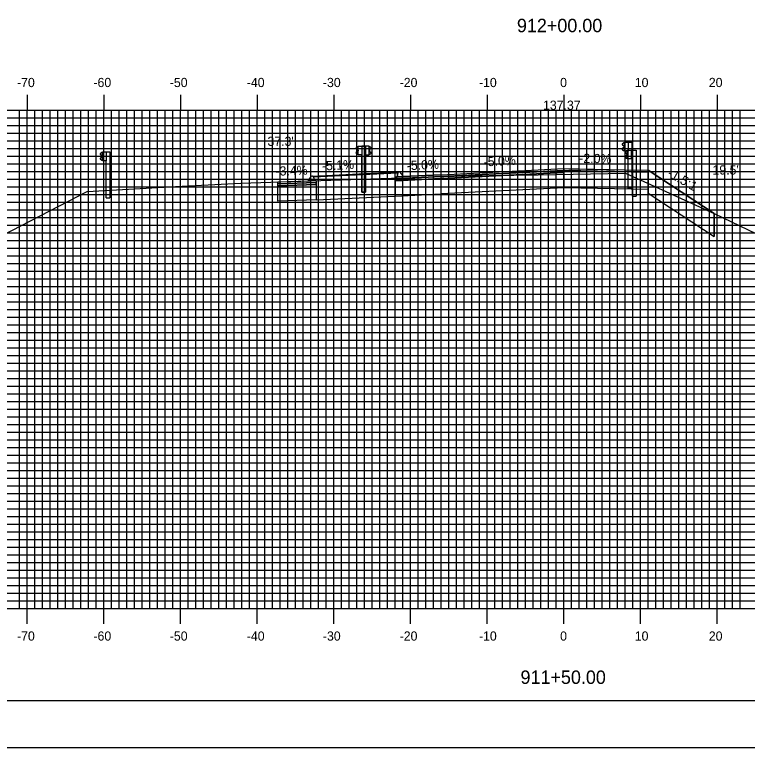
# Model space of a CAD drawing. Extents: x 859865 to 860208, y 364765 to 364985.
# Drawn here: x 859958.8 to 860054.3, y 364765.2 to 364860.7 of the extents above; entities that cross this region are included whole.
import ezdxf

# ---------------------------------------------------------------- set-up
doc = ezdxf.new("R2010")
doc.units = 0
for name, color, linetype in [('ANNOTATION', 7, 'Continuous'), ('BORDER', 7, 'Continuous'), ('D_Curb_Type_3M2_Lt', 7, 'Continuous'), ('D_Curb_Type_3M2_Rt', 7, 'Continuous'), ('D_Guardrail_Beam_Rt', 7, 'Continuous'), ('D_Roadway_Centerline', 7, 'Continuous'), ('D_Roadway_Centerline_Text', 7, 'Continuous'), ('D_Roadway_Edge_Shoulder', 7, 'Continuous'), ('D_Roadway_Edge_TW', 7, 'Continuous'), ('D_Roadway_FinishedGrade', 7, 'Continuous'), ('D_Roadway_Pavement', 7, 'Continuous'), ('D_Roadway_SubGrade', 7, 'Continuous'), ('D_Text_Standard', 7, 'Continuous'), ('H_V ANNOTATION', 7, 'Continuous'), ('M_Guardrail', 7, 'Continuous'), ('M_Roadway_Centerline', 7, 'Continuous'), ('MAJOR', 7, 'Continuous'), ('MINOR', 7, 'Continuous'), ('PATTERNING', 7, 'Continuous'), ('PLOT BOUNDARY', 7, 'Continuous'), ('S_Roadway_Centerline', 7, 'Continuous')]:
    doc.layers.add(name, color=color, linetype=linetype)

msp = doc.modelspace()

# ---------------------------------------------------------------- linework, layer by layer
at = {"layer": 'BORDER'}
msp.add_lwpolyline([(859880.786, 364771.302), (860200.786, 364771.302), (860200.786, 364981.302), (859880.786, 364981.302)], close=True, dxfattribs=at)
at = {"layer": 'D_Curb_Type_3M2_Lt'}
for p, q in [((860008.744, 364840.114), (860008.636, 364839.62)), ((860008.636, 364839.62), (860009.386, 364839.62)), ((860008.88, 364840.243), (860008.885, 364840.243)), ((860009.386, 364839.787), (860009.032, 364840.189)), ((860009.386, 364839.62), (860009.386, 364839.787))]:
    msp.add_line(p, q, dxfattribs=at)
msp.add_arc((860008.907, 364840.079), 0.167, 41.38705, 167.66476, dxfattribs=at)
at = {"layer": 'D_Curb_Type_3M2_Rt'}
for p, q in [((859997.1, 364839.245), (859997.454, 364839.647)), ((859997.742, 364839.572), (859997.85, 364839.078)), ((859997.1, 364839.078), (859997.1, 364839.245)), ((859997.85, 364839.078), (859997.1, 364839.078))]:
    msp.add_line(p, q, dxfattribs=at)
msp.add_arc((859997.579, 364839.537), 0.167, 12.33524, 138.61295, dxfattribs=at)
at = {"layer": 'D_Guardrail_Beam_Rt'}
for p, q in [((860038.567, 364842.989), (860038.423, 364842.889)), ((860038.423, 364842.746), (860038.619, 364842.61)), ((860038.619, 364842.411), (860038.423, 364842.275)), ((860038.657, 364843.01), (860038.583, 364842.996)), ((860038.652, 364842.545), (860038.652, 364842.475)), ((860038.657, 364843.094), (860039.344, 364843.094)), ((860038.657, 364841.927), (860038.657, 364843.094)), ((860039.177, 364843.094), (860039.177, 364841.927)), ((860039.282, 364843.094), (860039.282, 364841.927)), ((860039.344, 364843.094), (860039.815, 364843.094)), ((860039.344, 364843.094), (860039.344, 364841.927)), ((860039.815, 364843.094), (860039.815, 364837.094)), ((860038.423, 364842.131), (860038.567, 364842.032)), ((860038.583, 364842.025), (860038.657, 364842.01)), ((860039.344, 364841.927), (860038.657, 364841.927)), ((860039.323, 364837.094), (860039.323, 364841.927)), ((860039.323, 364837.094), (860039.815, 364837.094))]:
    msp.add_line(p, q, dxfattribs=at)
for centre, major_axis, start_param, end_param in [((860038.474, 364842.817), (-0.0877, 0), 5.323254, 7.243116), ((860038.591, 364842.955), (-0.0417, 0), 4.907132, 5.323254), ((860038.573, 364842.545), (0.0789, 0), 0, 0.959931), ((860038.573, 364842.475), (0.0789, 0), 5.323254, 6.283185), ((860038.474, 364842.203), (-0.0877, 0), 5.323254, 7.243116), ((860038.591, 364842.065), (-0.0417, 0), 0.959931, 1.376053)]:
    msp.add_ellipse(centre, major_axis=major_axis, ratio=0.995501, start_param=start_param, end_param=end_param, dxfattribs=at)
at = {"layer": 'D_Roadway_Centerline'}
for points in [[(860009.387, 364839.62), (860010.325, 364839.667), (860014.384, 364839.87), (860014.386, 364839.87), (860030.387, 364840.67), (860031.027, 364840.657), (860038.382, 364840.51), (860038.386, 364840.51), (860041.387, 364840.45), (860049.995, 364834.792)], [(859993.1, 364838.943), (859993.316, 364838.951), (859997.1, 364839.078)]]:
    msp.add_lwpolyline(points, dxfattribs=at)
at = {"layer": 'D_Roadway_Edge_Shoulder'}
for points in [[(860030.387, 364840.67), (860038.386, 364840.51), (860038.386, 364840.51), (860041.386, 364840.45), (860041.386, 364840.2), (860030.387, 364840.42)], [(860014.386, 364839.87), (860009.386, 364839.62), (860008.386, 364839.57), (860008.386, 364839.32), (860014.386, 364839.62)], [(859993.1, 364838.943), (859997.1, 364839.078), (859998.1, 364839.111), (859998.1, 364838.861), (859993.1, 364838.693)]]:
    msp.add_lwpolyline(points, close=True, dxfattribs=at)
at = {"layer": 'D_Roadway_Edge_TW'}
msp.add_lwpolyline([(860014.386, 364839.87), (860030.387, 364840.67), (860030.387, 364840.42), (860014.386, 364839.62)], close=True, dxfattribs=at)
at = {"layer": 'D_Roadway_FinishedGrade'}
msp.add_line((860049.995, 364834.792), (860049.995, 364831.792), dxfattribs=at)
for points in [[(860041.386, 364840.45), (860042.886, 364839.45), (860049.995, 364834.792)], [(860041.387, 364840.45), (860041.387, 364837.45), (860049.995, 364831.792)], [(859997.621, 364839.698), (860008.865, 364840.24)]]:
    msp.add_lwpolyline(points, dxfattribs=at)
at = {"layer": 'D_Roadway_Pavement'}
for points in [[(860014.386, 364839.62), (860030.387, 364840.42), (860030.387, 364840.17), (860014.386, 364839.37)], [(860014.386, 364839.62), (860008.386, 364839.32), (860008.386, 364839.07), (860014.386, 364839.37)], [(859993.1, 364838.693), (859998.1, 364838.861), (859998.1, 364838.611), (859993.1, 364838.443)]]:
    msp.add_lwpolyline(points, close=True, dxfattribs=at)
msp.add_lwpolyline([(860030.387, 364840.42), (860030.387, 364840.17)], dxfattribs=at)
msp.add_lwpolyline([(860030.387, 364840.42), (860030.387, 364840.17)], dxfattribs=at)
at = {"layer": 'D_Roadway_SubGrade'}
for points in [[(860030.387, 364840.17), (860030.387, 364840.42), (860041.386, 364840.2), (860041.386, 364840.45), (860041.387, 364837.95), (860030.387, 364838.17)], [(859998.1, 364839.111), (859998.1, 364836.611), (860008.386, 364837.07), (860008.386, 364839.07), (860008.386, 364839.32), (860008.386, 364839.57), (860008.628, 364839.582), (860008.734, 364840.067), (859997.75, 364839.534), (859997.845, 364839.103)], [(860014.386, 364839.37), (860030.387, 364840.17), (860030.387, 364838.17), (860014.386, 364837.37)], [(859993.1, 364838.443), (859998.1, 364838.611), (859998.1, 364838.861), (859998.1, 364836.611), (859993.1, 364836.443)], [(860014.386, 364839.37), (860008.386, 364839.07), (860008.386, 364839.32), (860008.386, 364837.07), (860014.386, 364837.37)]]:
    msp.add_lwpolyline(points, close=True, dxfattribs=at)
at = {"layer": 'M_Guardrail'}
for p, q in [((860003.459, 364843.517), (860003.316, 364843.417)), ((860003.316, 364843.274), (860003.511, 364843.138)), ((860003.558, 364843.538), (860003.476, 364843.524)), ((860003.558, 364843.611), (860004.048, 364843.611)), ((860003.558, 364842.445), (860003.558, 364843.611)), ((860004.035, 364843.612), (860004.035, 364837.612)), ((860004.527, 364843.612), (860004.035, 364843.612)), ((860004.048, 364843.611), (860004.539, 364843.611)), ((860004.048, 364843.611), (860004.048, 364842.445)), ((860005.017, 364843.612), (860004.527, 364843.612)), ((860004.527, 364843.612), (860004.527, 364842.445)), ((860004.539, 364843.611), (860004.539, 364837.611)), ((860005.017, 364842.445), (860005.017, 364843.612)), ((860005.017, 364843.539), (860005.099, 364843.525)), ((860005.259, 364843.275), (860005.063, 364843.139)), ((860005.115, 364843.518), (860005.259, 364843.418)), ((860038.18, 364844.01), (860038.036, 364843.91)), ((860038.036, 364843.767), (860038.232, 364843.631)), ((860038.232, 364843.411), (860038.036, 364843.275)), ((860038.279, 364844.031), (860038.197, 364844.017)), ((860038.265, 364843.566), (860038.265, 364843.475)), ((860038.279, 364844.104), (860038.768, 364844.104)), ((860038.279, 364842.938), (860038.279, 364844.104)), ((860038.768, 364844.104), (860039.26, 364844.104)), ((860038.768, 364844.104), (860038.768, 364842.938)), ((860039.26, 364844.104), (860039.26, 364838.104)), ((859970.108, 364842.76), (859969.964, 364842.66)), ((859969.964, 364842.517), (859970.16, 364842.38)), ((859970.206, 364842.781), (859970.124, 364842.766)), ((859970.193, 364842.316), (859970.193, 364842.225)), ((859970.206, 364842.854), (859970.696, 364842.854)), ((859970.206, 364841.687), (859970.206, 364842.854)), ((859970.696, 364842.854), (859971.188, 364842.854)), ((859970.696, 364842.854), (859970.696, 364841.687)), ((859971.188, 364842.854), (859971.188, 364836.854)), ((860003.511, 364842.918), (860003.316, 364842.782)), ((860003.316, 364842.639), (860003.459, 364842.539)), ((860003.476, 364842.532), (860003.558, 364842.517)), ((860003.545, 364843.073), (860003.545, 364842.982)), ((860004.048, 364842.445), (860003.558, 364842.445)), ((860004.048, 364837.611), (860004.048, 364842.445)), ((860004.527, 364837.612), (860004.527, 364842.445)), ((860004.527, 364842.445), (860005.017, 364842.445)), ((860005.099, 364842.533), (860005.017, 364842.518)), ((860005.03, 364843.074), (860005.03, 364842.983)), ((860005.063, 364842.919), (860005.259, 364842.783)), ((860005.259, 364842.64), (860005.115, 364842.54)), ((860038.036, 364843.132), (860038.18, 364843.032)), ((860038.197, 364843.025), (860038.279, 364843.011)), ((860038.768, 364842.938), (860038.279, 364842.938)), ((860038.768, 364838.104), (860038.768, 364842.938)), ((859970.16, 364842.161), (859969.964, 364842.024)), ((859969.964, 364841.881), (859970.108, 364841.781)), ((859970.124, 364841.774), (859970.206, 364841.76)), ((859970.696, 364841.687), (859970.206, 364841.687)), ((859970.696, 364836.854), (859970.696, 364841.687)), ((860004.527, 364837.612), (860004.035, 364837.612)), ((860004.048, 364837.611), (860004.539, 364837.611)), ((860038.768, 364838.104), (860039.26, 364838.104)), ((859970.696, 364836.854), (859971.188, 364836.854))]:
    msp.add_line(p, q, dxfattribs=at)
for centre, major_axis, start_param, end_param in [((860003.366, 364843.345), (-0.0877, 0), 5.323254, 7.243116), ((860003.483, 364843.483), (-0.0417, 0), 4.886922, 5.323254), ((860005.091, 364843.484), (0.0417, 0), 0.959931, 1.396263), ((860005.208, 364843.346), (0.0877, 0), 5.323254, 7.243116), ((860038.087, 364843.839), (-0.0877, 0), 5.323254, 7.243116), ((860038.087, 364843.203), (-0.0877, 0), 5.323254, 7.243116), ((860038.204, 364843.976), (-0.0417, 0), 4.886922, 5.323254), ((860038.187, 364843.566), (0.0789, 0), 0, 0.959931), ((860038.187, 364843.475), (0.0789, 0), 5.323254, 6.283185), ((859970.014, 364842.588), (-0.0877, 0), 5.323254, 7.243116), ((859970.132, 364842.726), (-0.0417, 0), 4.886922, 5.323254), ((859970.114, 364842.316), (0.0789, 0), 0, 0.959931), ((860003.366, 364842.71), (-0.0877, 0), 5.323254, 7.243116), ((860003.483, 364842.573), (-0.0417, 0), 0.959931, 1.396263), ((860003.466, 364843.073), (0.0789, 0), 0, 0.959931), ((860003.466, 364842.982), (0.0789, 0), 5.323254, 6.283185), ((860005.109, 364843.074), (-0.0789, 0), 5.323254, 6.283185), ((860005.109, 364842.983), (-0.0789, 0), 6.283185, 7.243116), ((860005.091, 364842.574), (0.0417, 0), 4.886922, 5.323254), ((860005.208, 364842.711), (0.0877, 0), 5.323254, 7.243116), ((860038.204, 364843.066), (-0.0417, 0), 0.959931, 1.396263), ((859970.014, 364841.953), (-0.0877, 0), 5.323254, 7.243116), ((859970.132, 364841.815), (-0.0417, 0), 0.959931, 1.396263), ((859970.114, 364842.225), (0.0789, 0), 5.323254, 6.283185)]:
    msp.add_ellipse(centre, major_axis=major_axis, ratio=0.995501, start_param=start_param, end_param=end_param, dxfattribs=at)
at = {"layer": 'MAJOR'}
for p, q in [((859960.386, 364850.306), (859960.386, 364848.302)), ((859970.386, 364850.306), (859970.386, 364848.302)), ((859980.386, 364850.306), (859980.386, 364848.302)), ((859990.386, 364850.306), (859990.386, 364848.302)), ((860000.386, 364850.306), (860000.386, 364848.302)), ((860010.386, 364850.306), (860010.386, 364848.302)), ((860020.386, 364850.306), (860020.386, 364848.302)), ((860030.386, 364850.306), (860030.386, 364848.302)), ((860040.386, 364850.306), (860040.386, 364848.302)), ((860050.386, 364850.306), (860050.386, 364848.302)), ((859890.386, 364848.302), (860170.386, 364848.302)), ((859890.386, 364848.302), (860170.386, 364848.302)), ((859960.386, 364783.302), (859960.386, 364848.302)), ((859970.386, 364783.302), (859970.386, 364848.302)), ((859980.386, 364783.302), (859980.386, 364848.302)), ((859990.386, 364783.302), (859990.386, 364848.302)), ((860000.386, 364783.302), (860000.386, 364848.302)), ((860010.386, 364783.302), (860010.386, 364848.302)), ((860020.386, 364783.302), (860020.386, 364848.302)), ((860030.386, 364783.302), (860030.386, 364848.302)), ((860040.386, 364783.302), (860040.386, 364848.302)), ((860050.386, 364783.302), (860050.386, 364848.302)), ((859890.386, 364843.302), (860170.386, 364843.302)), ((859890.386, 364838.302), (860170.386, 364838.302)), ((859890.386, 364833.302), (860170.386, 364833.302)), ((859890.386, 364828.302), (860170.386, 364828.302)), ((859890.386, 364823.302), (860170.386, 364823.302)), ((859890.386, 364818.302), (860170.386, 364818.302)), ((859890.386, 364813.302), (860170.386, 364813.302)), ((859890.386, 364808.302), (860170.386, 364808.302)), ((859890.386, 364803.302), (860170.386, 364803.302)), ((859890.386, 364798.302), (860170.386, 364798.302)), ((859890.386, 364793.302), (860170.386, 364793.302)), ((859890.386, 364788.302), (860170.386, 364788.302)), ((859890.386, 364783.302), (860170.386, 364783.302)), ((859890.386, 364783.302), (860170.386, 364783.302)), ((859960.386, 364781.298), (859960.386, 364783.302)), ((859970.386, 364781.298), (859970.386, 364783.302)), ((859980.386, 364781.298), (859980.386, 364783.302)), ((859990.386, 364781.298), (859990.386, 364783.302)), ((860000.386, 364781.298), (860000.386, 364783.302)), ((860010.386, 364781.298), (860010.386, 364783.302)), ((860020.386, 364781.298), (860020.386, 364783.302)), ((860030.386, 364781.298), (860030.386, 364783.302)), ((860040.386, 364781.298), (860040.386, 364783.302)), ((860050.386, 364781.298), (860050.386, 364783.302))]:
    msp.add_line(p, q, dxfattribs=at)
at = {"layer": 'MINOR'}
for p, q in [((859959.386, 364783.302), (859959.386, 364848.302)), ((859961.386, 364783.302), (859961.386, 364848.302)), ((859962.386, 364783.302), (859962.386, 364848.302)), ((859963.386, 364783.302), (859963.386, 364848.302)), ((859964.386, 364783.302), (859964.386, 364848.302)), ((859965.386, 364783.302), (859965.386, 364848.302)), ((859966.386, 364783.302), (859966.386, 364848.302)), ((859967.386, 364783.302), (859967.386, 364848.302)), ((859968.386, 364783.302), (859968.386, 364848.302)), ((859969.386, 364783.302), (859969.386, 364848.302)), ((859971.386, 364783.302), (859971.386, 364848.302)), ((859972.386, 364783.302), (859972.386, 364848.302)), ((859973.386, 364783.302), (859973.386, 364848.302)), ((859974.386, 364783.302), (859974.386, 364848.302)), ((859975.386, 364783.302), (859975.386, 364848.302)), ((859976.386, 364783.302), (859976.386, 364848.302)), ((859977.386, 364783.302), (859977.386, 364848.302)), ((859978.386, 364783.302), (859978.386, 364848.302)), ((859979.386, 364783.302), (859979.386, 364848.302)), ((859981.386, 364783.302), (859981.386, 364848.302)), ((859982.386, 364783.302), (859982.386, 364848.302)), ((859983.386, 364783.302), (859983.386, 364848.302)), ((859984.386, 364783.302), (859984.386, 364848.302)), ((859985.386, 364783.302), (859985.386, 364848.302)), ((859986.386, 364783.302), (859986.386, 364848.302)), ((859987.386, 364783.302), (859987.386, 364848.302)), ((859988.386, 364783.302), (859988.386, 364848.302)), ((859989.386, 364783.302), (859989.386, 364848.302)), ((859991.386, 364783.302), (859991.386, 364848.302)), ((859992.386, 364783.302), (859992.386, 364848.302)), ((859993.386, 364783.302), (859993.386, 364848.302)), ((859994.386, 364783.302), (859994.386, 364848.302)), ((859995.386, 364783.302), (859995.386, 364848.302)), ((859996.386, 364783.302), (859996.386, 364848.302)), ((859997.386, 364783.302), (859997.386, 364848.302)), ((859998.386, 364783.302), (859998.386, 364848.302)), ((859999.386, 364783.302), (859999.386, 364848.302)), ((860001.386, 364783.302), (860001.386, 364848.302)), ((860002.386, 364783.302), (860002.386, 364848.302)), ((860003.386, 364783.302), (860003.386, 364848.302)), ((860004.386, 364783.302), (860004.386, 364848.302)), ((860005.386, 364783.302), (860005.386, 364848.302)), ((860006.386, 364783.302), (860006.386, 364848.302)), ((860007.386, 364783.302), (860007.386, 364848.302)), ((860008.386, 364783.302), (860008.386, 364848.302)), ((860009.386, 364783.302), (860009.386, 364848.302)), ((860011.386, 364783.302), (860011.386, 364848.302)), ((860012.386, 364783.302), (860012.386, 364848.302)), ((860013.386, 364783.302), (860013.386, 364848.302)), ((860014.386, 364783.302), (860014.386, 364848.302)), ((860015.386, 364783.302), (860015.386, 364848.302)), ((860016.386, 364783.302), (860016.386, 364848.302)), ((860017.386, 364783.302), (860017.386, 364848.302)), ((860018.386, 364783.302), (860018.386, 364848.302)), ((860019.386, 364783.302), (860019.386, 364848.302)), ((860021.386, 364783.302), (860021.386, 364848.302)), ((860022.386, 364783.302), (860022.386, 364848.302)), ((860023.386, 364783.302), (860023.386, 364848.302)), ((860024.386, 364783.302), (860024.386, 364848.302)), ((860025.386, 364783.302), (860025.386, 364848.302)), ((860026.386, 364783.302), (860026.386, 364848.302)), ((860027.386, 364783.302), (860027.386, 364848.302)), ((860028.386, 364783.302), (860028.386, 364848.302)), ((860029.386, 364783.302), (860029.386, 364848.302)), ((860031.386, 364783.302), (860031.386, 364848.302)), ((860032.386, 364783.302), (860032.386, 364848.302)), ((860033.386, 364783.302), (860033.386, 364848.302)), ((860034.386, 364783.302), (860034.386, 364848.302)), ((860035.386, 364783.302), (860035.386, 364848.302)), ((860036.386, 364783.302), (860036.386, 364848.302)), ((860037.386, 364783.302), (860037.386, 364848.302)), ((860038.386, 364783.302), (860038.386, 364848.302)), ((860039.386, 364783.302), (860039.386, 364848.302)), ((860041.386, 364783.302), (860041.386, 364848.302)), ((860042.386, 364783.302), (860042.386, 364848.302)), ((860043.386, 364783.302), (860043.386, 364848.302)), ((860044.386, 364783.302), (860044.386, 364848.302)), ((860045.386, 364783.302), (860045.386, 364848.302)), ((860046.386, 364783.302), (860046.386, 364848.302)), ((860047.386, 364783.302), (860047.386, 364848.302)), ((860048.386, 364783.302), (860048.386, 364848.302)), ((860049.386, 364783.302), (860049.386, 364848.302)), ((860051.386, 364783.302), (860051.386, 364848.302)), ((860052.386, 364783.302), (860052.386, 364848.302)), ((860053.386, 364783.302), (860053.386, 364848.302)), ((859890.386, 364847.302), (860170.386, 364847.302)), ((859890.386, 364846.302), (860170.386, 364846.302)), ((859890.386, 364845.302), (860170.386, 364845.302)), ((859890.386, 364844.302), (860170.386, 364844.302)), ((859890.386, 364842.302), (860170.386, 364842.302)), ((859890.386, 364841.302), (860170.386, 364841.302)), ((859890.386, 364840.302), (860170.386, 364840.302)), ((859890.386, 364839.302), (860170.386, 364839.302)), ((859890.386, 364837.302), (860170.386, 364837.302)), ((859890.386, 364836.302), (860170.386, 364836.302)), ((859890.386, 364835.302), (860170.386, 364835.302)), ((859890.386, 364834.302), (860170.386, 364834.302)), ((859890.386, 364832.302), (860170.386, 364832.302)), ((859890.386, 364831.302), (860170.386, 364831.302)), ((859890.386, 364830.302), (860170.386, 364830.302)), ((859890.386, 364829.302), (860170.386, 364829.302)), ((859890.386, 364827.302), (860170.386, 364827.302)), ((859890.386, 364826.302), (860170.386, 364826.302)), ((859890.386, 364825.302), (860170.386, 364825.302)), ((859890.386, 364824.302), (860170.386, 364824.302)), ((859890.386, 364822.302), (860170.386, 364822.302)), ((859890.386, 364821.302), (860170.386, 364821.302)), ((859890.386, 364820.302), (860170.386, 364820.302)), ((859890.386, 364819.302), (860170.386, 364819.302)), ((859890.386, 364817.302), (860170.386, 364817.302)), ((859890.386, 364816.302), (860170.386, 364816.302)), ((859890.386, 364815.302), (860170.386, 364815.302)), ((859890.386, 364814.302), (860170.386, 364814.302)), ((859890.386, 364812.302), (860170.386, 364812.302)), ((859890.386, 364811.302), (860170.386, 364811.302)), ((859890.386, 364810.302), (860170.386, 364810.302)), ((859890.386, 364809.302), (860170.386, 364809.302)), ((859890.386, 364807.302), (860170.386, 364807.302)), ((859890.386, 364806.302), (860170.386, 364806.302)), ((859890.386, 364805.302), (860170.386, 364805.302)), ((859890.386, 364804.302), (860170.386, 364804.302)), ((859890.386, 364802.302), (860170.386, 364802.302)), ((859890.386, 364801.302), (860170.386, 364801.302)), ((859890.386, 364800.302), (860170.386, 364800.302)), ((859890.386, 364799.302), (860170.386, 364799.302)), ((859890.386, 364797.302), (860170.386, 364797.302)), ((859890.386, 364796.302), (860170.386, 364796.302)), ((859890.386, 364795.302), (860170.386, 364795.302)), ((859890.386, 364794.302), (860170.386, 364794.302)), ((859890.386, 364792.302), (860170.386, 364792.302)), ((859890.386, 364791.302), (860170.386, 364791.302)), ((859890.386, 364790.302), (860170.386, 364790.302)), ((859890.386, 364789.302), (860170.386, 364789.302)), ((859890.386, 364787.302), (860170.386, 364787.302)), ((859890.386, 364786.302), (860170.386, 364786.302)), ((859890.386, 364785.302), (860170.386, 364785.302)), ((859890.386, 364784.302), (860170.386, 364784.302))]:
    msp.add_line(p, q, dxfattribs=at)
at = {"layer": 'PATTERNING'}
for p, q in [((860041.387, 364837.95), (860041.387, 364837.45)), ((860041.387, 364837.45), (860049.995, 364831.792)), ((860049.995, 364831.792), (860049.995, 364834.792))]:
    msp.add_line(p, q, dxfattribs=at)
for points in [[(860049.995, 364834.792), (860042.886, 364839.45), (860041.386, 364840.45)], [(860041.386, 364840.45), (860041.386, 364840.2), (860041.387, 364837.95), (860041.387, 364837.95)]]:
    msp.add_lwpolyline(points, dxfattribs=at)
at = {"layer": 'PLOT BOUNDARY'}
msp.add_lwpolyline([(859864.6, 364765.184), (860204.6, 364765.184), (860204.6, 364985.184), (859864.6, 364985.184)], close=True, dxfattribs=at)
at = {"layer": 'S_Roadway_Centerline'}
msp.add_lwpolyline([(859890.386, 364812.971), (859894.391, 364812.833), (859897.423, 364812.789), (859905.344, 364812.655), (859915.458, 364814.796), (859929.437, 364819.075), (859934.194, 364820.746), (859958.408, 364832.58), (859968.226, 364837.682), (859979.732, 364838.329), (859988.281, 364838.781), (860006.532, 364839.396), (860017.485, 364839.72), (860027.043, 364839.866), (860038.428, 364840.091), (860049.995, 364834.792), (860076.156, 364822.232)], dxfattribs=at)

# ---------------------------------------------------------------- texts
at = {"layer": 'ANNOTATION'}
for s, rotation, p in [('-5.0%', 2.86232, (860019.957, 364840.951)), ('-2.0%', 358.85419, (860032.39, 364841.431)), ('-5.1%', 2.90693, (859998.869, 364840.413)), ('-5.0%', 2.86198, (860009.925, 364840.45)), ('-3.4%', 1.93169, (859992.799, 364839.734)), ('-1.5:1', 330.177, (860043.791, 364839.736))]:
    msp.add_text(s, height=1.2, rotation=rotation, dxfattribs=at).set_placement(p)
at = {"layer": 'D_Roadway_Centerline_Text'}
msp.add_text('137.37', height=1.2, dxfattribs=at).set_placement((860027.668, 364848.339))
at = {"layer": 'D_Text_Standard'}
for s, p in [("37.3'", (859991.736, 364843.633)), ("19.5'", (860049.777, 364839.895))]:
    msp.add_text(s, height=1.2, dxfattribs=at).set_placement(p)
at = {"layer": 'H_V ANNOTATION'}
for s, height, p in [('912+00.00', 1.75, (860024.269, 364858.458)), ('-70', 1.2, (859959.069, 364851.302)), ('-60', 1.2, (859969.038, 364851.302)), ('-50', 1.2, (859978.995, 364851.302)), ('-40', 1.2, (859989.038, 364851.302)), ('-30', 1.2, (859998.963, 364851.302)), ('-20', 1.2, (860008.973, 364851.302)), ('-10', 1.2, (860019.316, 364851.302)), ('0', 1.2, (860029.904, 364851.302)), ('10', 1.2, (860039.637, 364851.302)), ('20', 1.2, (860049.294, 364851.302)), ('-70', 1.2, (859959.069, 364779.102)), ('-60', 1.2, (859969.038, 364779.102)), ('-50', 1.2, (859978.995, 364779.102)), ('-40', 1.2, (859989.038, 364779.102)), ('-30', 1.2, (859998.963, 364779.102)), ('-20', 1.2, (860008.973, 364779.102)), ('-10', 1.2, (860019.316, 364779.102)), ('0', 1.2, (860029.904, 364779.102)), ('10', 1.2, (860039.637, 364779.102)), ('20', 1.2, (860049.294, 364779.102)), ('911+50.00', 1.75, (860024.737, 364773.458))]:
    msp.add_text(s, height=height, dxfattribs=at).set_placement(p)
at = {"layer": 'M_Roadway_Centerline'}
for s, p in [('C', (860017.48, 364839.72)), ('L', (860017.485, 364839.712)), ('C', (859988.275, 364838.781)), ('L', (859988.281, 364838.774))]:
    msp.add_text(s, height=0.0146, dxfattribs=at).set_placement(p)

doc.saveas('drawing.dxf')
